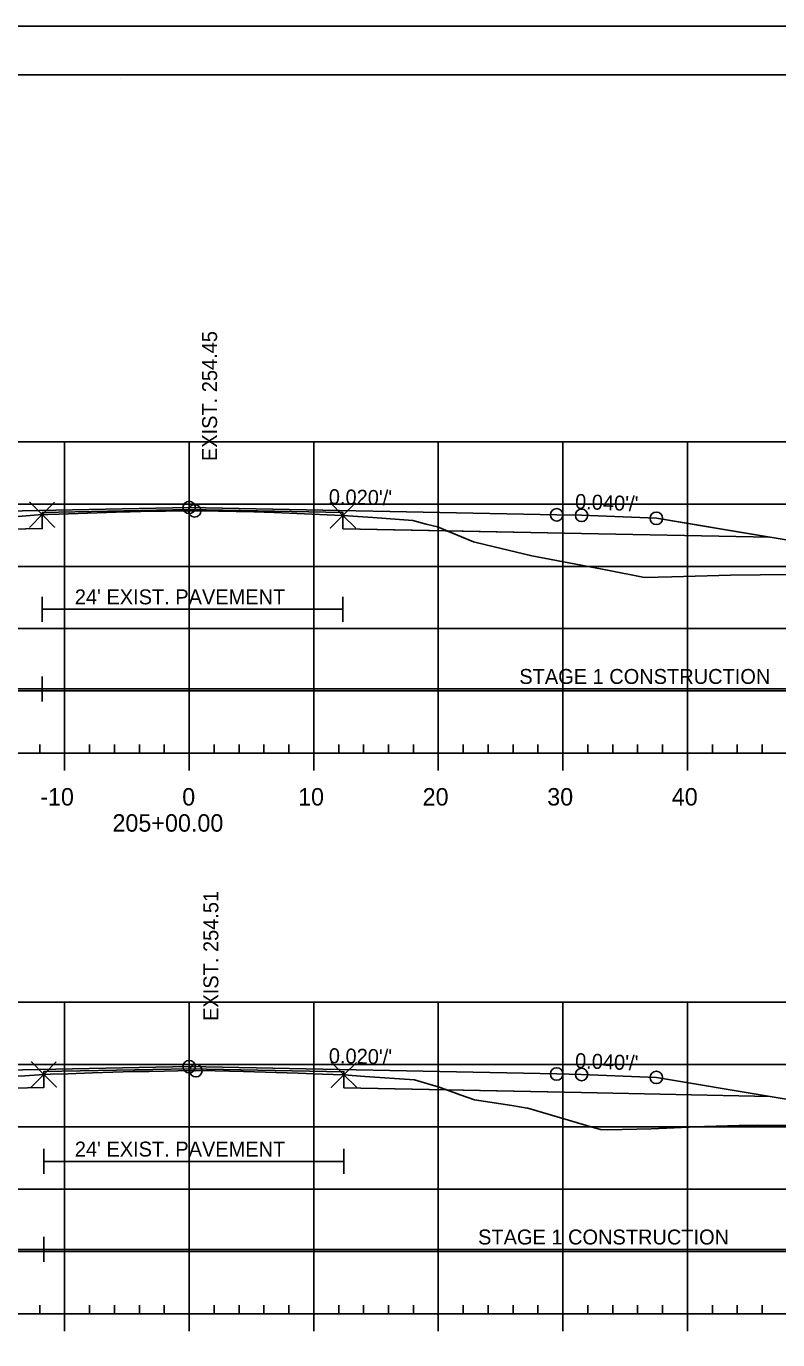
# Model space of a CAD drawing. Extents: x 1365647 to 1367999, y 387113 to 400173.
# Drawn here: x 1365881 to 1365941.3, y 390040.7 to 390146.1 of the extents above; entities that cross this region are included whole.
import ezdxf

# ---------------------------------------------------------------- set-up
doc = ezdxf.new("R2010")
doc.units = 0
for name, color, linetype in [('R_Alt Surface', 7, 'Continuous'), ('R_Axis', 7, 'Continuous'), ('R_Axis Annot', 7, 'Continuous'), ('R_Border', 7, 'Continuous'), ('R_Contours', 7, 'Continuous'), ('R_Exist Surface', 7, 'Continuous'), ('R_Fin Surface', 7, 'Continuous'), ('R_Fin Surface Annot', 7, 'Continuous'), ('R_Grid', 7, 'Continuous'), ('R_No Plot', 7, 'Continuous'), ('R_Water', 7, 'Continuous'), ('R_Xsect Elev', 7, 'Continuous')]:
    doc.layers.add(name, color=color, linetype=linetype)

msp = doc.modelspace()

# ---------------------------------------------------------------- linework, layer by layer
at = {"layer": 'R_Alt Surface'}
for points in [[(1365847.47, 390105.1), (1365862.59, 390105.41), (1365882.29, 390105.8), (1365882.29, 390107.09), (1365894.09, 390107.33), (1365906.43, 390107.08), (1365906.43, 390105.79), (1365925.59, 390105.41), (1365940.72, 390105.1)], [(1365847.47, 390060.22), (1365862.59, 390060.52), (1365882.42, 390060.92), (1365882.42, 390062.21), (1365894.09, 390062.44), (1365906.51, 390062.19), (1365906.51, 390060.91), (1365925.59, 390060.52), (1365940.72, 390060.22)]]:
    msp.add_lwpolyline(points, dxfattribs=at)
at = {"layer": 'R_Axis'}
for p, q in [((1365749.09, 390087.77), (1366039.09, 390087.77)), ((1365882.09, 390087.77), (1365882.09, 390088.47)), ((1365884.09, 390086.37), (1365884.09, 390087.77)), ((1365886.09, 390087.77), (1365886.09, 390088.47)), ((1365888.09, 390087.77), (1365888.09, 390088.47)), ((1365890.09, 390087.77), (1365890.09, 390088.47)), ((1365892.09, 390087.77), (1365892.09, 390088.47)), ((1365894.09, 390086.37), (1365894.09, 390087.77)), ((1365896.09, 390087.77), (1365896.09, 390088.47)), ((1365898.09, 390087.77), (1365898.09, 390088.47)), ((1365900.09, 390087.77), (1365900.09, 390088.47)), ((1365902.09, 390087.77), (1365902.09, 390088.47)), ((1365904.09, 390086.37), (1365904.09, 390087.77)), ((1365906.09, 390087.77), (1365906.09, 390088.47)), ((1365908.09, 390087.77), (1365908.09, 390088.47)), ((1365910.09, 390087.77), (1365910.09, 390088.47)), ((1365912.09, 390087.77), (1365912.09, 390088.47)), ((1365914.09, 390086.37), (1365914.09, 390087.77)), ((1365916.09, 390087.77), (1365916.09, 390088.47)), ((1365918.09, 390087.77), (1365918.09, 390088.47)), ((1365920.09, 390087.77), (1365920.09, 390088.47)), ((1365922.09, 390087.77), (1365922.09, 390088.47)), ((1365924.09, 390086.37), (1365924.09, 390087.77)), ((1365926.09, 390087.77), (1365926.09, 390088.47)), ((1365928.09, 390087.77), (1365928.09, 390088.47)), ((1365930.09, 390087.77), (1365930.09, 390088.47)), ((1365932.09, 390087.77), (1365932.09, 390088.47)), ((1365934.09, 390086.37), (1365934.09, 390087.77)), ((1365936.09, 390087.77), (1365936.09, 390088.47)), ((1365938.09, 390087.77), (1365938.09, 390088.47)), ((1365940.09, 390087.77), (1365940.09, 390088.47)), ((1365882.09, 390042.77), (1365882.09, 390043.47)), ((1365886.09, 390042.77), (1365886.09, 390043.47)), ((1365888.09, 390042.77), (1365888.09, 390043.47)), ((1365890.09, 390042.77), (1365890.09, 390043.47)), ((1365892.09, 390042.77), (1365892.09, 390043.47)), ((1365896.09, 390042.77), (1365896.09, 390043.47)), ((1365898.09, 390042.77), (1365898.09, 390043.47)), ((1365900.09, 390042.77), (1365900.09, 390043.47)), ((1365902.09, 390042.77), (1365902.09, 390043.47)), ((1365906.09, 390042.77), (1365906.09, 390043.47)), ((1365908.09, 390042.77), (1365908.09, 390043.47)), ((1365910.09, 390042.77), (1365910.09, 390043.47)), ((1365912.09, 390042.77), (1365912.09, 390043.47)), ((1365916.09, 390042.77), (1365916.09, 390043.47)), ((1365918.09, 390042.77), (1365918.09, 390043.47)), ((1365920.09, 390042.77), (1365920.09, 390043.47)), ((1365922.09, 390042.77), (1365922.09, 390043.47)), ((1365926.09, 390042.77), (1365926.09, 390043.47)), ((1365928.09, 390042.77), (1365928.09, 390043.47)), ((1365930.09, 390042.77), (1365930.09, 390043.47)), ((1365932.09, 390042.77), (1365932.09, 390043.47)), ((1365936.09, 390042.77), (1365936.09, 390043.47)), ((1365938.09, 390042.77), (1365938.09, 390043.47)), ((1365940.09, 390042.77), (1365940.09, 390043.47)), ((1365749.09, 390042.77), (1366039.09, 390042.77)), ((1365884.09, 390041.37), (1365884.09, 390042.77)), ((1365894.09, 390041.37), (1365894.09, 390042.77)), ((1365904.09, 390041.37), (1365904.09, 390042.77)), ((1365914.09, 390041.37), (1365914.09, 390042.77)), ((1365924.09, 390041.37), (1365924.09, 390042.77)), ((1365934.09, 390041.37), (1365934.09, 390042.77))]:
    msp.add_line(p, q, dxfattribs=at)
at = {"layer": 'R_Border'}
for p, q in [((1365736.09, 390142.23), (1366052.27, 390142.23)), ((1365888.61, 390141.97), (1365888.61, 390141.97)), ((1365888.61, 390141.97), (1365888.61, 390141.97))]:
    msp.add_line(p, q, dxfattribs=at)
at = {"layer": 'R_Contours'}
for p, q in [((1365906.43, 390106.86), (1365906.43, 390105.79)), ((1365906.43, 390105.79), (1365914.78, 390105.62)), ((1365906.51, 390061.95), (1365906.51, 390060.91)), ((1365906.51, 390060.91), (1365914.76, 390060.74))]:
    msp.add_line(p, q, dxfattribs=at)
for points in [[(1365872.83, 390105.61), (1365874.84, 390106.26), (1365875.71, 390106.36), (1365876.85, 390106.55), (1365880.04, 390106.75), (1365882.29, 390106.92), (1365882.29, 390105.8)], [(1365882.29, 390106.92), (1365882.6, 390106.94), (1365882.73, 390106.94), (1365883.65, 390106.97), (1365888.97, 390107.14), (1365889.36, 390107.15), (1365890.22, 390107.16), (1365894.18, 390107.22), (1365894.53, 390107.22), (1365894.81, 390107.23), (1365895.02, 390107.23), (1365899.27, 390107.15), (1365900.92, 390107.1), (1365905.77, 390106.89), (1365906.43, 390106.86), (1365906.43, 390107.08), (1365894.09, 390107.33), (1365882.29, 390107.09)], [(1365906.43, 390106.86), (1365908.83, 390106.68), (1365912.03, 390106.44), (1365913.12, 390106.16), (1365914.02, 390105.95), (1365914.34, 390105.81), (1365914.78, 390105.62), (1365906.43, 390105.79)], [(1365914.78, 390105.62), (1365916.92, 390104.74), (1365917.89, 390104.51), (1365921.59, 390103.62), (1365927.68, 390102.46), (1365930.64, 390101.88), (1365932.84, 390101.93), (1365937.54, 390102.07), (1365944.66, 390102.15), (1365944.82, 390102.15), (1365944.84, 390102.15), (1365946.25, 390102.03), (1365948.7, 390102.24), (1365949.02, 390102.27), (1365949.96, 390102.42), (1365951.58, 390102.67), (1365952.43, 390102.93), (1365953.14, 390103.03), (1365940.72, 390105.1), (1365925.59, 390105.41)], [(1365870.63, 390060.69), (1365872.3, 390061.03), (1365874.71, 390061.2), (1365875.38, 390061.3), (1365877.02, 390061.67), (1365880.89, 390061.87), (1365882.42, 390061.98), (1365882.42, 390060.92)], [(1365882.42, 390061.98), (1365882.95, 390062), (1365884.37, 390062.03), (1365886.34, 390062.1), (1365887.97, 390062.15), (1365889.61, 390062.21), (1365890.88, 390062.22), (1365892.08, 390062.24), (1365893.17, 390062.27), (1365894.52, 390062.29), (1365894.63, 390062.28), (1365895.04, 390062.29), (1365898.45, 390062.21), (1365902.83, 390062.08), (1365904.79, 390062), (1365906.51, 390061.95), (1365906.51, 390062.19), (1365894.09, 390062.44), (1365882.42, 390062.21)], [(1365906.51, 390061.95), (1365908.2, 390061.82), (1365912.17, 390061.54), (1365913.43, 390061.17), (1365914.09, 390060.99), (1365914.76, 390060.74), (1365906.51, 390060.91)], [(1365914.76, 390060.74), (1365915.83, 390060.35), (1365917, 390059.95), (1365920, 390059.48), (1365921.22, 390059.28), (1365921.27, 390059.27), (1365926.44, 390057.75), (1365927.11, 390057.55), (1365927.7, 390057.54), (1365931.18, 390057.62), (1365935.45, 390057.8), (1365938.24, 390057.89), (1365939.73, 390057.92), (1365941.56, 390057.89), (1365943.03, 390057.9), (1365943.8, 390057.87), (1365944.22, 390057.85), (1365945.84, 390057.77), (1365949.89, 390058.69), (1365940.72, 390060.22), (1365925.59, 390060.52)]]:
    msp.add_lwpolyline(points, close=True, dxfattribs=at)
for points in [[(1365914.78, 390105.62), (1365914.34, 390105.81), (1365914.02, 390105.95), (1365913.12, 390106.16), (1365912.03, 390106.44), (1365908.83, 390106.68), (1365906.43, 390106.86)], [(1365914.76, 390060.74), (1365914.09, 390060.99), (1365913.43, 390061.17), (1365912.17, 390061.54), (1365908.2, 390061.82), (1365906.51, 390061.95)]]:
    msp.add_lwpolyline(points, dxfattribs=at)
at = {"layer": 'R_Exist Surface'}
for points in [[(1365880.04, 390106.75), (1365882.29, 390106.92), (1365882.6, 390106.94), (1365882.73, 390106.94), (1365883.65, 390106.97), (1365888.97, 390107.14), (1365889.36, 390107.15), (1365890.22, 390107.16), (1365894.18, 390107.22), (1365894.53, 390107.22), (1365894.81, 390107.23), (1365895.02, 390107.23), (1365899.27, 390107.15), (1365900.92, 390107.1), (1365905.77, 390106.89), (1365906.43, 390106.86), (1365908.83, 390106.68), (1365912.03, 390106.44), (1365913.12, 390106.16), (1365914.02, 390105.95), (1365914.34, 390105.81), (1365916.92, 390104.74), (1365917.89, 390104.51), (1365921.59, 390103.62), (1365927.68, 390102.46), (1365930.64, 390101.88), (1365932.84, 390101.93), (1365937.54, 390102.07), (1365944.66, 390102.15)], [(1365880.89, 390061.87), (1365882.42, 390061.98), (1365882.95, 390062), (1365884.37, 390062.03), (1365886.34, 390062.1), (1365887.97, 390062.15), (1365889.61, 390062.21), (1365890.88, 390062.22), (1365892.08, 390062.24), (1365893.17, 390062.27), (1365894.52, 390062.29), (1365894.63, 390062.28), (1365895.04, 390062.29), (1365898.45, 390062.21), (1365902.83, 390062.08), (1365904.79, 390062), (1365906.51, 390061.95), (1365908.2, 390061.82), (1365912.17, 390061.54), (1365913.43, 390061.17), (1365914.09, 390060.99), (1365915.83, 390060.35), (1365917, 390059.95), (1365920, 390059.48), (1365921.22, 390059.28), (1365921.27, 390059.27), (1365926.44, 390057.75), (1365927.11, 390057.55), (1365927.7, 390057.54), (1365931.18, 390057.62), (1365935.45, 390057.8), (1365938.24, 390057.89), (1365939.73, 390057.92), (1365941.56, 390057.89)]]:
    msp.add_lwpolyline(points, dxfattribs=at)
at = {"layer": 'R_Fin Surface'}
for points in [[(1365822.31, 390102.5), (1365827.77, 390100.68), (1365834.59, 390102.96), (1365847.47, 390105.1), (1365856.59, 390106.63), (1365862.59, 390106.87), (1365864.59, 390106.91), (1365894.09, 390107.5), (1365923.59, 390106.91), (1365925.59, 390106.87), (1365931.59, 390106.63), (1365940.72, 390105.1), (1365953.59, 390102.96), (1365965.89, 390098.86), (1365979.23, 390103.31)], [(1365832.74, 390102.34), (1365834.59, 390102.96), (1365852.3, 390105.91), (1365856.59, 390106.63), (1365862.59, 390106.87), (1365864.59, 390106.91), (1365894.09, 390107.5), (1365923.59, 390106.91), (1365925.59, 390106.87), (1365931.59, 390106.63), (1365935.89, 390105.91), (1365953.59, 390102.96), (1365954.16, 390103.15)], [(1365856.59, 390106.63), (1365862.59, 390106.87), (1365864.59, 390106.91), (1365894.09, 390107.5), (1365923.59, 390106.91), (1365925.59, 390106.87), (1365931.59, 390106.63)], [(1365830.21, 390059.53), (1365834.58, 390058.07), (1365834.59, 390058.08), (1365847.47, 390060.22), (1365856.59, 390061.74), (1365862.59, 390061.98), (1365864.59, 390062.02), (1365894.09, 390062.61), (1365923.59, 390062.02), (1365925.59, 390061.98), (1365931.59, 390061.74), (1365940.72, 390060.22), (1365953.59, 390058.08), (1365959.42, 390056.13), (1365973.57, 390060.85)], [(1365856.59, 390061.74), (1365862.59, 390061.98), (1365864.59, 390062.02), (1365894.09, 390062.61), (1365923.59, 390062.02), (1365925.59, 390061.98), (1365931.59, 390061.74)]]:
    msp.add_lwpolyline(points, dxfattribs=at)
at = {"layer": 'R_Grid'}
for p, q in [((1365749.09, 390112.77), (1366039.09, 390112.77)), ((1365884.09, 390087.77), (1365884.09, 390112.77)), ((1365894.09, 390087.77), (1365894.09, 390112.77)), ((1365904.09, 390087.77), (1365904.09, 390112.77)), ((1365914.09, 390087.77), (1365914.09, 390112.77)), ((1365924.09, 390087.77), (1365924.09, 390112.77)), ((1365934.09, 390087.77), (1365934.09, 390112.77)), ((1365749.09, 390107.77), (1366039.09, 390107.77)), ((1365749.09, 390102.77), (1366039.09, 390102.77)), ((1365749.09, 390097.77), (1366039.09, 390097.77)), ((1365749.09, 390092.77), (1366039.09, 390092.77)), ((1365749.09, 390087.77), (1366039.09, 390087.77)), ((1365749.09, 390067.77), (1366039.09, 390067.77)), ((1365884.09, 390042.77), (1365884.09, 390067.77)), ((1365894.09, 390042.77), (1365894.09, 390067.77)), ((1365904.09, 390042.77), (1365904.09, 390067.77)), ((1365914.09, 390042.77), (1365914.09, 390067.77)), ((1365924.09, 390042.77), (1365924.09, 390067.77)), ((1365934.09, 390042.77), (1365934.09, 390067.77)), ((1365749.09, 390062.77), (1366039.09, 390062.77)), ((1365749.09, 390057.77), (1366039.09, 390057.77)), ((1365749.09, 390052.77), (1366039.09, 390052.77)), ((1365749.09, 390047.77), (1366039.09, 390047.77)), ((1365749.09, 390042.77), (1366039.09, 390042.77))]:
    msp.add_line(p, q, dxfattribs=at)
at = {"layer": 'R_No Plot'}
msp.add_line((1365723.69, 390146.13), (1366057.03, 390146.13), dxfattribs=at)
msp.add_lwpolyline([(1365723.69, 390146.13), (1366057.03, 390146.13), (1366057.03, 389932.79), (1365723.69, 389932.79)], close=True, dxfattribs=at)
for points in [[(1365882.29, 390106.92), (1365881.29, 390107.92), (1365882.29, 390106.92), (1365881.29, 390105.92), (1365882.29, 390106.92), (1365883.29, 390105.92), (1365882.29, 390106.92), (1365883.29, 390107.92)], [(1365906.43, 390106.86), (1365905.43, 390107.86), (1365906.43, 390106.86), (1365905.43, 390105.86), (1365906.43, 390106.86), (1365907.43, 390105.86), (1365906.43, 390106.86), (1365907.43, 390107.86)], [(1365882.42, 390061.98), (1365881.42, 390062.98), (1365882.42, 390061.98), (1365881.42, 390060.98), (1365882.42, 390061.98), (1365883.42, 390060.98), (1365882.42, 390061.98), (1365883.42, 390062.98)], [(1365906.51, 390061.95), (1365905.51, 390062.95), (1365906.51, 390061.95), (1365905.51, 390060.95), (1365906.51, 390061.95), (1365907.51, 390060.95), (1365906.51, 390061.95), (1365907.51, 390062.95)]]:
    msp.add_lwpolyline(points, dxfattribs=at)
for centre in [(1365894.09, 390107.5), (1365894.09, 390107.5), (1365894.09, 390107.5), (1365894.09, 390107.5), (1365894.09, 390107.5), (1365894.53, 390107.22), (1365923.59, 390106.91), (1365923.59, 390106.91), (1365923.59, 390106.91), (1365923.59, 390106.91), (1365923.59, 390106.91), (1365925.59, 390106.87), (1365925.59, 390106.87), (1365925.59, 390106.87), (1365925.59, 390106.87), (1365925.59, 390106.87), (1365931.59, 390106.63), (1365931.59, 390106.63), (1365931.59, 390106.63), (1365931.59, 390106.63), (1365931.59, 390106.63), (1365894.09, 390062.61), (1365894.09, 390062.61), (1365894.09, 390062.61), (1365894.09, 390062.61), (1365894.09, 390062.61), (1365894.63, 390062.28), (1365923.59, 390062.02), (1365923.59, 390062.02), (1365923.59, 390062.02), (1365923.59, 390062.02), (1365923.59, 390062.02), (1365925.59, 390061.98), (1365925.59, 390061.98), (1365925.59, 390061.98), (1365925.59, 390061.98), (1365925.59, 390061.98), (1365931.59, 390061.74), (1365931.59, 390061.74), (1365931.59, 390061.74), (1365931.59, 390061.74), (1365931.59, 390061.74)]:
    msp.add_circle(centre, 0.5, dxfattribs=at)
at = {"layer": 'R_Water'}
for p, q in [((1365882.29, 390098.32), (1365882.29, 390100.32)), ((1365906.43, 390098.32), (1365906.43, 390100.32)), ((1365882.29, 390099.32), (1365906.43, 390099.32)), ((1365882.29, 390091.93), (1365882.29, 390093.93)), ((1365822.31, 390092.93), (1365882.29, 390092.93)), ((1365882.29, 390092.93), (1365979.23, 390092.93)), ((1365882.42, 390054), (1365882.42, 390056)), ((1365906.51, 390054), (1365906.51, 390056)), ((1365882.42, 390055), (1365906.51, 390055)), ((1365882.42, 390046.94), (1365882.42, 390048.94)), ((1365830.21, 390047.94), (1365882.42, 390047.94)), ((1365882.42, 390047.94), (1365973.57, 390047.94))]:
    msp.add_line(p, q, dxfattribs=at)

# ---------------------------------------------------------------- texts
at = {"layer": 'R_Axis Annot'}
for s, p in [('-10', (1365882.13, 390083.57)), ('0', (1365893.53, 390083.57)), ('10', (1365902.83, 390083.57)), ('20', (1365912.83, 390083.57)), ('30', (1365922.83, 390083.57)), ('40', (1365932.83, 390083.57)), ('205+00.00', (1365887.93, 390081.47))]:
    msp.add_text(s, height=1.4, dxfattribs=at).set_placement(p)
at = {"layer": 'R_Fin Surface Annot'}
for s, rotation, p in [("0.020'/'", 358.8542, (1365905.29, 390107.77)), ("0.040'/'", 357.7094, (1365925.05, 390107.39)), ("0.020'/'", 358.8542, (1365905.29, 390062.89)), ("0.040'/'", 357.7094, (1365925.05, 390062.5))]:
    msp.add_text(s, height=1.2, rotation=rotation, dxfattribs=at).set_placement(p)
at = {"layer": 'R_Water'}
for s, p in [("24' EXIST. PAVEMENT", (1365884.91, 390099.72)), ('STAGE 1 CONSTRUCTION', (1365920.59, 390093.33)), ("24' EXIST. PAVEMENT", (1365884.91, 390055.39)), ('STAGE 1 CONSTRUCTION', (1365917.28, 390048.33))]:
    msp.add_text(s, height=1.2, dxfattribs=at).set_placement(p)
at = {"layer": 'R_Xsect Elev'}
for s, p in [('EXIST. 254.45', (1365896.33, 390111.22)), ('EXIST. 254.51', (1365896.43, 390066.28))]:
    msp.add_text(s, height=1.2, rotation=90, dxfattribs=at).set_placement(p)

doc.saveas('drawing.dxf')
